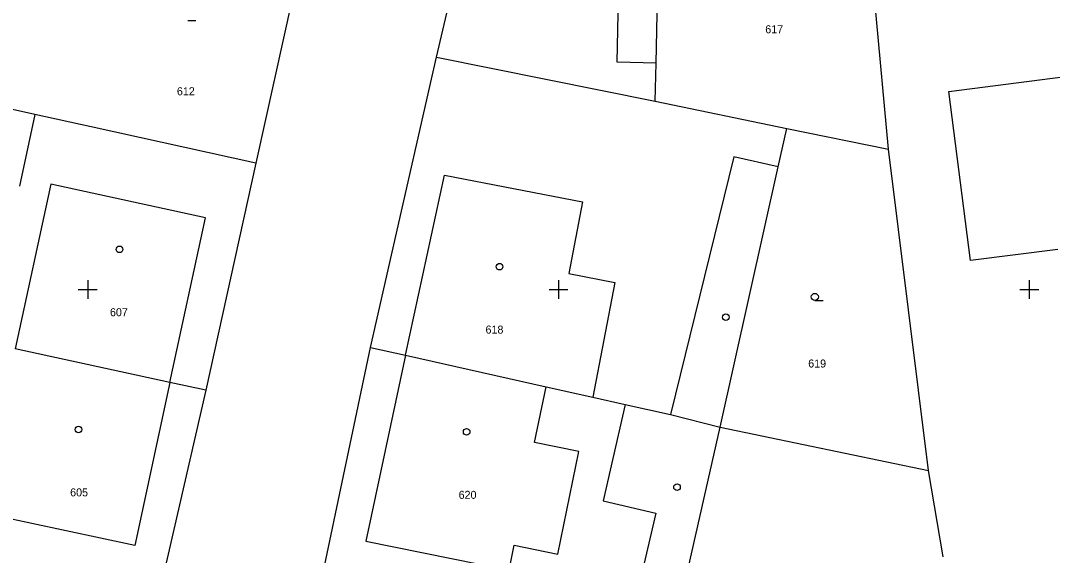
# Model space of a CAD drawing. Extents: x -702257 to -701487, y -1009871 to -1008841.
# Drawn here: x -701728.6 to -701673.8, y -1009439.1 to -1009410.7 of the extents above; entities that cross this region are included whole.
import ezdxf

# ---------------------------------------------------------------- set-up
doc = ezdxf.new("R2010")
doc.units = 0
for name, color, linetype in [('Z_hektometricka_sit', 7, 'Continuous'), ('Z_katastr_cisla_pozemkova', 7, 'Continuous'), ('Z_katastr_cisla_stavebni', 7, 'Continuous'), ('Z_katastr_hranice', 7, 'Continuous'), ('Z_katastr_vnitrni_kresba', 7, 'Continuous'), ('Z_katastr_znacky_budov', 7, 'Continuous'), ('Z_katastr_znacky_kultur', 7, 'Continuous')]:
    doc.layers.add(name, color=color, linetype=linetype)

msp = doc.modelspace()

# ---------------------------------------------------------------- linework, layer by layer
at = {"layer": 'Z_hektometricka_sit'}
for p, q in [((-701725, -1009424.5), (-701725, -1009425.5)), ((-701725, -1009424.5), (-701725, -1009425.5)), ((-701700, -1009424.5), (-701700, -1009425.5)), ((-701700, -1009424.5), (-701700, -1009425.5)), ((-701675, -1009424.5), (-701675, -1009425.5)), ((-701675, -1009424.5), (-701675, -1009425.5)), ((-701725.5, -1009425), (-701724.5, -1009425)), ((-701725.5, -1009425), (-701724.5, -1009425)), ((-701700.5, -1009425), (-701699.5, -1009425)), ((-701700.5, -1009425), (-701699.5, -1009425)), ((-701675.5, -1009425), (-701674.5, -1009425)), ((-701675.5, -1009425), (-701674.5, -1009425))]:
    msp.add_line(p, q, dxfattribs=at)
at = {"layer": 'Z_katastr_hranice'}
for p, q in [((-701711.4, -1009397.2), (-701716.07, -1009418.3)), ((-701706.47, -1009412.66), (-701703.2, -1009398.42)), ((-701682.47, -1009417.56), (-701683.9, -1009402.02)), ((-701694.82, -1009412.98), (-701694.7, -1009407.61)), ((-701709.98, -1009428.07), (-701706.47, -1009412.66)), ((-701706.47, -1009412.66), (-701694.87, -1009415.01)), ((-701694.87, -1009415.01), (-701694.82, -1009412.98)), ((-701679.27, -1009414.49), (-701671.86, -1009413.53)), ((-701678.13, -1009423.46), (-701679.27, -1009414.49)), ((-701694.87, -1009415.01), (-701687.88, -1009416.46)), ((-701727.8, -1009415.72), (-701730.19, -1009415.19)), ((-701724.82, -1009416.37), (-701727.8, -1009415.72)), ((-701716.07, -1009418.3), (-701724.82, -1009416.37)), ((-701688.33, -1009418.49), (-701687.88, -1009416.46)), ((-701687.88, -1009416.46), (-701682.47, -1009417.56)), ((-701680.36, -1009434.61), (-701682.47, -1009417.56)), ((-701716.07, -1009418.3), (-701718.72, -1009430.34)), ((-701691.41, -1009432.3), (-701688.33, -1009418.49)), ((-701673.48, -1009422.88), (-701678.13, -1009423.46)), ((-701720.64, -1009429.93), (-701728.85, -1009428.15)), ((-701713.08, -1009442.77), (-701709.98, -1009428.07)), ((-701709.98, -1009428.07), (-701708.12, -1009428.49)), ((-701708.12, -1009428.49), (-701700.66, -1009430.16)), ((-701718.72, -1009430.34), (-701721.46, -1009442.19)), ((-701718.72, -1009430.34), (-701720.64, -1009429.93)), ((-701700.66, -1009430.16), (-701698.17, -1009430.72)), ((-701698.17, -1009430.72), (-701696.46, -1009431.1)), ((-701696.46, -1009431.1), (-701694.06, -1009431.64)), ((-701694.06, -1009431.64), (-701691.41, -1009432.3)), ((-701693.59, -1009441.86), (-701691.41, -1009432.3)), ((-701691.41, -1009432.3), (-701680.36, -1009434.61)), ((-701679.58, -1009439.18), (-701680.36, -1009434.61))]:
    msp.add_line(p, q, dxfattribs=at)
at = {"layer": 'Z_katastr_vnitrni_kresba'}
for p, q in [((-701696.89, -1009412.93), (-701696.8, -1009408.81)), ((-701694.82, -1009412.98), (-701696.89, -1009412.93)), ((-701727.8, -1009415.72), (-701728.63, -1009419.52)), ((-701690.69, -1009417.96), (-701694.06, -1009431.64)), ((-701688.33, -1009418.49), (-701690.69, -1009417.96)), ((-701726.96, -1009419.41), (-701728.85, -1009428.15)), ((-701718.75, -1009421.19), (-701726.96, -1009419.41)), ((-701708.12, -1009428.49), (-701706.06, -1009418.94)), ((-701706.06, -1009418.94), (-701698.72, -1009420.34)), ((-701698.72, -1009420.34), (-701699.46, -1009424.15)), ((-701720.64, -1009429.93), (-701718.75, -1009421.19)), ((-701699.46, -1009424.15), (-701697.01, -1009424.63)), ((-701697.01, -1009424.63), (-701698.17, -1009430.72)), ((-701708.12, -1009428.49), (-701710.24, -1009438.35)), ((-701720.64, -1009429.93), (-701722.5, -1009438.59)), ((-701701.27, -1009433.12), (-701700.66, -1009430.16)), ((-701696.46, -1009431.1), (-701697.63, -1009436.22)), ((-701698.92, -1009433.6), (-701701.27, -1009433.12)), ((-701700.03, -1009439.04), (-701698.92, -1009433.6)), ((-701697.63, -1009436.22), (-701694.83, -1009436.87)), ((-701722.5, -1009438.59), (-701730.64, -1009436.85)), ((-701694.83, -1009436.87), (-701695.89, -1009441.39)), ((-701710.24, -1009438.35), (-701702.62, -1009439.9)), ((-701702.62, -1009439.9), (-701702.35, -1009438.57)), ((-701702.35, -1009438.57), (-701700.03, -1009439.04))]:
    msp.add_line(p, q, dxfattribs=at)
at = {"layer": 'Z_katastr_znacky_budov'}
for centre in [(-701723.307, -1009422.869), (-701703.127, -1009423.789), (-701691.117, -1009426.469), (-701725.487, -1009432.429), (-701704.877, -1009432.559), (-701693.707, -1009435.489)]:
    msp.add_circle(centre, 0.175, dxfattribs=at)
at = {"layer": 'Z_katastr_znacky_kultur'}
for p, q in [((-701719.688, -1009410.73), (-701719.251, -1009410.73)), ((-701686.388, -1009425.58), (-701685.951, -1009425.58))]:
    msp.add_line(p, q, dxfattribs=at)
msp.add_circle((-701686.388, -1009425.392), 0.187, dxfattribs=at)

# ---------------------------------------------------------------- texts
at = {"layer": 'Z_katastr_cisla_pozemkova'}
for s, p in [('617', (-701689.02, -1009411.4)), ('612', (-701720.264, -1009414.69)), ('619', (-701686.739, -1009429.14))]:
    msp.add_text(s, height=0.425, dxfattribs=at).set_placement(p)
at = {"layer": 'Z_katastr_cisla_stavebni'}
for s, p in [('607', (-701723.818, -1009426.419)), ('618', (-701703.874, -1009427.34)), ('605', (-701725.933, -1009435.98)), ('620', (-701705.303, -1009436.11))]:
    msp.add_text(s, height=0.425, dxfattribs=at).set_placement(p)

doc.saveas('drawing.dxf')
